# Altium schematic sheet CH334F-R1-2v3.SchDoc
size 209 x 148 mm; PageSetup: Record=PageOptions¦CenterHorizontal=True¦CenterVertical=True¦PrintScale=0.65¦XCorrection=1.00¦YCorrection=1.00¦PrintKind=1¦BorderSize=5000000¦LeftOffset=0¦BottomOffset=0¦Orientation=2¦PaperLength=1000¦PaperWidth=1000¦Scale=100¦PaperSource=7¦PrintQuality=-4¦MediaType=1¦DitherType=10¦PaperKind=16 开 195x270¦PrintScaleMode=1
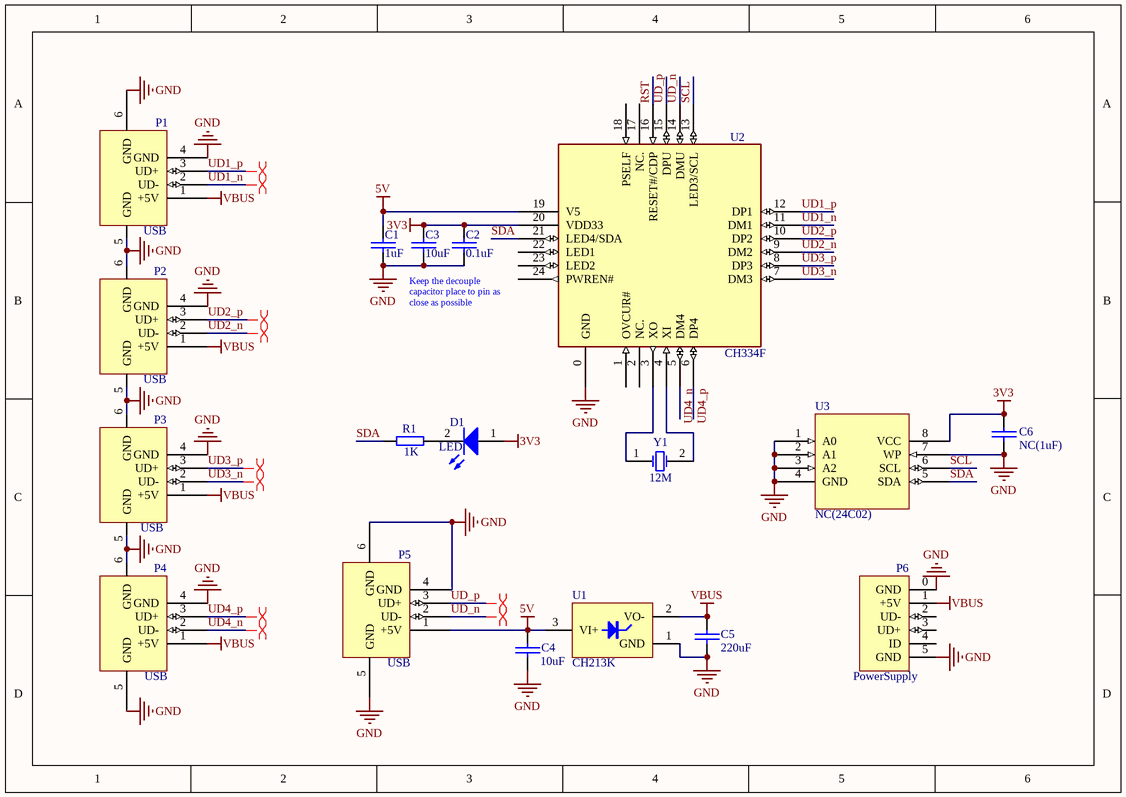
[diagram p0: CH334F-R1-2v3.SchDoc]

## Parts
C1  1uF  [0603_C]
C2  0.1uF  [0603_C]
C3  10uF  [0603_C]
C4  10uF  [0603_C]
C5  220uF  [CD0.1]
C6  NC(1uF)  [0603_C]
D1  LED  [0603+]
P1  USB  [USB2.0-A-F-TH_4P-V_13.7mm]
P2  USB  [USB2.0-A-F-TH_4P-V_13.7mm]
P3  USB  [USB2.0-A-F-TH_4P-V_13.7mm]
P4  USB  [USBAF]
P5  USB  [USBAF]
P6  PowerSupply  [USBMICROB-02-GXPX-A1T2]
R1  1K  [0603_R]
U1  CH213K  [SOT-23-3]
U2  CH334F  [QFN24_4X4]
U3  NC(24C02)  [SOIC-8_150mil]
Y1  12M  [XT_AT49]

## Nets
3V3: C2.1 C3.1 C6.1 D1.1(A) U2.20(VDD33) U3.8(VCC)
5V: C1.1 C4.1 P5.1(+5V) U1.3(VI+) U2.19(V5)
GND: C1.2 C2.2 C3.2 C4.2 C5.2 C6.2 P1.4(GND) P1.5(GND) P1.6(GND) P2.4(GND) P2.5(GND) P2.6(GND) P3.4(GND) P3.5(GND) P3.6(GND) P4.4(GND) P4.5(GND) P4.6(GND) P5.4(GND) P5.5(GND) P5.6(GND) P6.0(GND) P6.5(GND) U1.1(GND) U2.0(GND) U3.1(A0) U3.2(A1) U3.3(A2) U3.4(GND) U3.7(WP)
VBUS: C5.1 P1.1(+5V) P2.1(+5V) P3.1(+5V) P4.1(+5V) P6.1(+5V) U1.2(VO-)
RST: U2.16(RESET#/CDP)
SCL: U2.13(LED3/SCL) U3.6(SCL)
SDA: R1.1 U2.21(LED4/SDA) U3.5(SDA)
UD1_n: P1.2(UD-) U2.11(DM1)
UD1_p: P1.3(UD+) U2.12(DP1)
UD2_n: P2.2(UD-) U2.9(DM2)
UD2_p: P2.3(UD+) U2.10(DP2)
UD3_n: P3.2(UD-) U2.7(DM3)
UD3_p: P3.3(UD+) U2.8(DP3)
UD4_n: P4.2(UD-) U2.5(DM4)
UD4_p: P4.3(UD+) U2.6(DP4)
UD_n: P5.2(UD-) U2.14(DMU)
UD_p: P5.3(UD+) U2.15(DPU)
NetD1_2: D1.2(K) R1.2
NetU2_3: U2.3(XO) Y1.1(OSC1)
NetU2_4: U2.4(XI) Y1.2(OSC2)

Not connected (* = marked no-connect by the designer): P6 2(UD-) 3(UD+) 4(ID); U2 1(OVCUR#) 2(NC.) 17(NC.) 18(PSELF) 22(LED1) 23(LED2) 24(PWREN#)

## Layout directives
differential pair: UD1_n, UD1_p, UD2_n, UD2_p, UD3_n, UD3_p, UD4_n, UD4_p, UD_n, UD_p

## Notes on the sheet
- Keep the decouple capacitor place to pin as close as possible

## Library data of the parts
C1-C6 = CAP: Capacitor
D1 = LED: Typical INFRARED GaAs LED
P1-P5 = USB: USB Port
P6 = MicroUSB: MicroUSB Port
R1 = RES
U1 = CH213K: Ideal Diode 5V*1A
U2 = CH334F: 4 ports High-Speed USB MTT Hub with over current detect & power control
U3 = 24C01
Y1 = XTAL: Crystal Oscillator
